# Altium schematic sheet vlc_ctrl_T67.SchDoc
size Letter
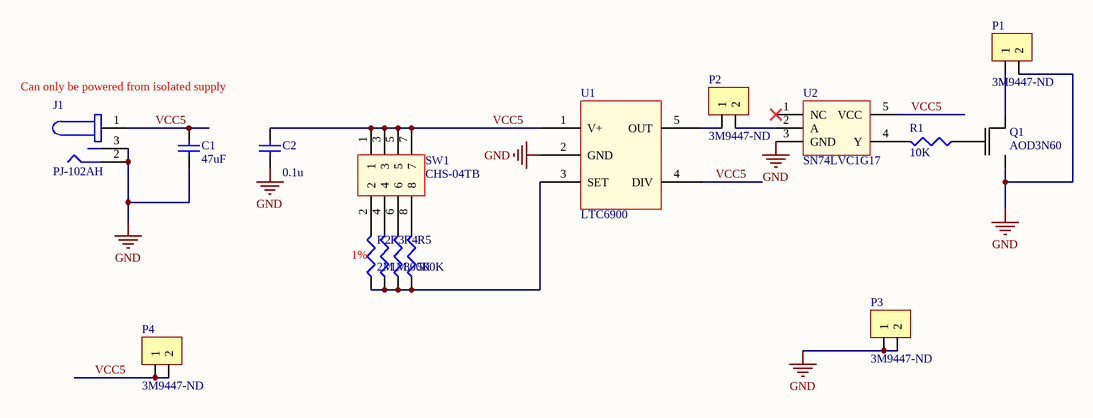
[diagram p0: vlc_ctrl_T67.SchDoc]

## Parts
C1  value 47uF  [C1210]  (hidden comment: Cap Semi)
C2  value 0.1u  [1608[0603]]  (hidden comment: Cap Semi)
J1  PJ-102AH  [PJ-102AH]
P1  Supplier Part Number 1: 3M9447-ND  [1x2 header]  (hidden comment: 1 x 2 header)
P2  Supplier Part Number 1: 3M9447-ND  [1x2 header]  (hidden comment: 1 x 2 header)
P3  Supplier Part Number 1: 3M9447-ND  [1x2 header]  (hidden comment: 1 x 2 header)
P4  Supplier Part Number 1: 3M9447-ND  [1x2 header]  (hidden comment: 1 x 2 header)
Q1  AOD3N60  [TO252]
R1  value 10K  [J1-0603]  (hidden comment: Res3)
R2  value 2M  [J1-0603]  (hidden comment: Res3)
R3  value 1M  [J1-0603]  (hidden comment: Res3)
R4  value 800K  [J1-0603]  (hidden comment: Res3)
R5  value 500K  [J1-0603]  (hidden comment: Res3)
SW1  CHS-04TB  [CHS04TB]
U1  LTC6900  [TSOT23]
U2  SN74LVC1G17  [SOT23-5]

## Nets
GND: C1.1 C2.1 J1.2 J1.3 P1.2 P3.1 P3.2 Q1.3(S) U1.2(GND) U2.3(GND)
VCC5: C1.2 C2.2 J1.1 P4.1 P4.2 SW1.1 SW1.3 SW1.5 SW1.7 U1.1(V+) U1.4(DIV) U2.5(VCC)
NetP1_1: P1.1 Q1.4(D)
NetP2_1: P2.1 U1.5(OUT)
NetP2_2: P2.2 U2.2(A)
NetQ1_1: Q1.1(G) R1.1
NetR1_2: R1.2 U2.4(Y)
NetR2_1: R2.1 R3.1 R4.1 R5.1 U1.3(SET)
NetR2_2: R2.2 SW1.2
NetR3_2: R3.2 SW1.4
NetR4_2: R4.2 SW1.6
NetR5_2: R5.2 SW1.8

Not connected (* = marked no-connect by the designer): U2 1(NC)*

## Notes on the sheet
- Can only be powered from isolated supply
- (near R2) 1%

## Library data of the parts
C1 C2 = Cap Semi: Capacitor (Semiconductor SIM Model)
J1 = PJ-102AH: CONN PWR JACK 2.1X5.5MM HIGH CUR
P1-P4 = 1 x 2 header: 100 mils standard header
Q1 = AOD3N60: 600V,2.5A N-Channel MOSFET
R1-R5 = Res3: Resistor
SW1 = CHS-04TB: SLIDE SWITCHES
U1 = LTC6900: Low Power, 1kHz to 20MHz   Resistor Set SOT-23 Oscillator
U2 = SN74LVC1G17: SINGLE SCHMITT-TRIGGER BUFFER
